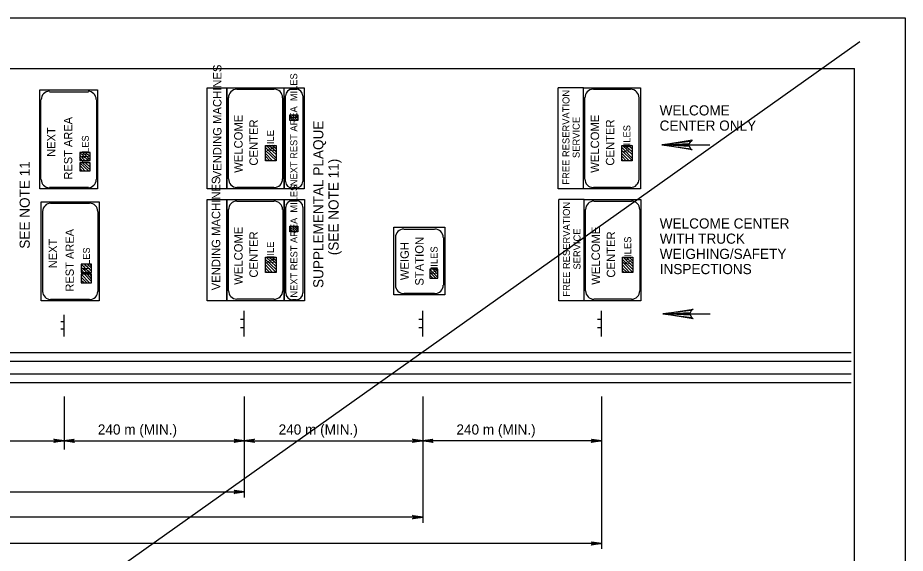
# Model space of a CAD drawing. Extents: x 2189973 to 2192941, y 2147557 to 2151454.
# Drawn here: x 2191872 to 2192732, y 2150935 to 2151454 of the extents above; entities that cross this region are included whole.
import ezdxf

# ---------------------------------------------------------------- set-up
doc = ezdxf.new("R2010")
doc.units = 0
for name, color, linetype in [('1', 7, 'Continuous'), ('Default', 7, 'Continuous'), ('PLT-BNDY', 7, 'Continuous')]:
    doc.layers.add(name, color=color, linetype=linetype)

# ---------------------------------------------------------------- blocks, each defined once
blk = doc.blocks.new('RARROW')
at = {"layer": 'Default'}
blk.add_lwpolyline([(-18.156, 2.28), (-17.479, 0.966), (0, 0), (-18.156, 2.28), (-19.086, 3.077), (0, 0), (-17.465, -0.864), (-18.103, -2.164), (0, 0), (-19.086, -3.033), (-18.103, -2.164)], dxfattribs=at)

msp = doc.modelspace()

# ---------------------------------------------------------------- linework, layer by layer
at = {"layer": '1'}
msp.add_line((2192688.33, 2151431.03), (2190039.06, 2149549.03), dxfattribs=at)
at = {"layer": 'Default'}
for p, q in [((2190104.48, 2151405.2), (2192683.21, 2151405.2)), ((2192683.21, 2149554.81), (2192683.21, 2151405.2)), ((2191893.03, 2151288.32), (2191893.03, 2151384.28)), ((2191893.03, 2151384.28), (2191949.21, 2151384.28)), ((2191902.46, 2151382.64), (2191940.19, 2151382.64)), ((2191949.21, 2151384.28), (2191949.21, 2151288.32)), ((2192074.62, 2151288.32), (2192074.62, 2151386.33)), ((2192074.62, 2151386.33), (2192129.98, 2151386.33)), ((2192084.05, 2151385.1), (2192120.14, 2151385.1)), ((2192138, 2151385.21), (2192141.59, 2151385.21)), ((2192395.73, 2151288.32), (2192395.73, 2151386.33)), ((2192420.34, 2151386.33), (2192395.73, 2151386.33)), ((2192420.34, 2151288.32), (2192420.34, 2151386.33)), ((2192420.34, 2151386.33), (2192475.7, 2151386.33)), ((2192430.18, 2151385.1), (2192465.86, 2151385.1)), ((2192475.7, 2151386.33), (2192475.7, 2151288.32)), ((2191894.26, 2151297.34), (2191894.26, 2151374.85)), ((2191947.98, 2151374.85), (2191947.98, 2151297.34)), ((2192076.26, 2151298.16), (2192076.26, 2151376.9)), ((2192128.59, 2151376.79), (2192128.59, 2151298.05)), ((2192129.98, 2151377.51), (2192129.98, 2151288.32)), ((2192131.4, 2151295.47), (2192131.4, 2151378.62)), ((2192148.18, 2151378.62), (2192148.18, 2151295.47)), ((2192421.57, 2151298.16), (2192421.57, 2151376.9)), ((2192474.06, 2151376.9), (2192474.06, 2151298.16)), ((2192140.89, 2151354.67), (2192135.57, 2151359.99)), ((2192138.73, 2151354.67), (2192135.57, 2151357.83)), ((2192136.57, 2151354.67), (2192135.57, 2151355.67)), ((2192143.06, 2151354.67), (2192137.48, 2151360.24)), ((2192143.31, 2151356.58), (2192139.64, 2151360.24)), ((2192143.31, 2151358.74), (2192141.81, 2151360.24)), ((2192496.21, 2151330.97), (2192542.96, 2151330.97)), ((2191949.21, 2151288.32), (2191893.03, 2151288.32)), ((2191940.19, 2151289.55), (2191902.46, 2151289.55)), ((2192129.98, 2151288.32), (2192074.62, 2151288.32)), ((2192120.14, 2151289.55), (2192084.05, 2151289.55)), ((2192141.65, 2151289.17), (2192138.06, 2151289.17)), ((2192420.34, 2151288.32), (2192395.73, 2151288.32)), ((2192475.7, 2151288.32), (2192420.34, 2151288.32)), ((2192465.86, 2151289.55), (2192430.18, 2151289.55)), ((2192055.35, 2151179.64), (2192055.35, 2151278.07)), ((2192055.35, 2151278.07), (2192074.62, 2151278.07)), ((2192074.62, 2151179.64), (2192074.62, 2151278.07)), ((2192074.62, 2151278.07), (2192129.98, 2151278.07)), ((2192074.62, 2151278.07), (2192074.62, 2151179.64)), ((2192129.98, 2151278.07), (2192129.98, 2151179.64)), ((2192129.98, 2151278.07), (2192129.98, 2151179.64)), ((2192138.16, 2151277.04), (2192141.75, 2151277.04)), ((2192396.55, 2151179.64), (2192396.55, 2151278.07)), ((2192421.16, 2151278.07), (2192396.55, 2151278.07)), ((2192421.16, 2151179.64), (2192421.16, 2151278.07)), ((2192421.16, 2151278.07), (2192476.11, 2151278.07)), ((2192476.11, 2151278.07), (2192476.11, 2151179.64)), ((2191894.54, 2151179.64), (2191894.54, 2151275.6)), ((2191894.54, 2151275.6), (2191950.72, 2151275.6)), ((2191903.56, 2151274.37), (2191941.29, 2151274.37)), ((2191950.72, 2151275.6), (2191950.72, 2151179.64)), ((2192084.05, 2151276.42), (2192120.14, 2151276.42)), ((2192131.57, 2151187.3), (2192131.57, 2151270.44)), ((2192148.35, 2151270.44), (2192148.35, 2151187.3)), ((2192430.59, 2151276.42), (2192467.09, 2151276.42)), ((2191896.18, 2151188.66), (2191896.18, 2151266.17)), ((2191949.49, 2151266.17), (2191949.49, 2151188.66)), ((2192076.26, 2151189.48), (2192076.26, 2151268.22)), ((2192128.75, 2151268.22), (2192128.75, 2151189.48)), ((2192422.39, 2151189.48), (2192422.39, 2151268.22)), ((2192474.88, 2151268.22), (2192474.88, 2151189.48)), ((2192141.06, 2151246.5), (2192135.73, 2151251.82)), ((2192143.22, 2151246.5), (2192137.65, 2151252.07)), ((2192143.47, 2151248.4), (2192139.81, 2151252.07)), ((2192143.47, 2151250.57), (2192141.97, 2151252.07)), ((2192138.89, 2151246.5), (2192135.73, 2151249.66)), ((2192136.73, 2151246.5), (2192135.73, 2151247.5)), ((2192236.61, 2151185.38), (2192236.61, 2151251)), ((2192236.61, 2151251), (2192285.82, 2151251)), ((2192246.45, 2151249.36), (2192275.98, 2151249.36)), ((2192285.82, 2151251), (2192285.82, 2151185.38)), ((2192238.25, 2151194.81), (2192238.25, 2151241.16)), ((2192284.59, 2151241.16), (2192284.59, 2151194.81)), ((2192285.82, 2151185.38), (2192236.61, 2151185.38)), ((2192275.98, 2151186.61), (2192246.45, 2151186.61)), ((2191950.72, 2151179.64), (2191894.54, 2151179.64)), ((2191941.29, 2151180.87), (2191903.56, 2151180.87)), ((2192074.62, 2151179.64), (2192055.35, 2151179.64)), ((2192129.98, 2151179.64), (2192074.62, 2151179.64)), ((2192120.14, 2151181.28), (2192084.05, 2151181.28)), ((2192141.75, 2151180.7), (2192138.16, 2151180.7)), ((2192421.16, 2151179.64), (2192396.55, 2151179.64)), ((2192476.11, 2151179.64), (2192421.16, 2151179.64)), ((2192467.09, 2151181.28), (2192430.59, 2151181.28)), ((2191916.68, 2151145.19), (2191916.68, 2151166.11)), ((2192091.43, 2151145.19), (2192091.43, 2151169.8)), ((2192264.5, 2151145.19), (2192264.5, 2151169.8)), ((2192437.97, 2151145.19), (2192437.97, 2151169.8)), ((2192497.22, 2151167.03), (2192543.15, 2151167.03)), ((2191916.68, 2151159.14), (2191913.4, 2151159.14)), ((2192091.43, 2151161.6), (2192087.74, 2151161.6)), ((2192264.5, 2151161.6), (2192260.81, 2151161.6)), ((2192437.97, 2151161.6), (2192433.87, 2151161.6)), ((2191916.68, 2151152.16), (2191913.4, 2151152.16)), ((2192091.43, 2151153.39), (2192087.74, 2151153.39)), ((2192264.5, 2151153.39), (2192260.81, 2151153.39)), ((2192437.97, 2151153.39), (2192433.87, 2151153.39)), ((2191186.33, 2151129.61), (2192679.93, 2151129.61)), ((2192509.33, 2151129.61), (2192509.33, 2151129.61)), ((2190114.32, 2151121), (2192679.93, 2151121)), ((2190114.32, 2151108.69), (2192679.93, 2151108.69)), ((2190114.32, 2151100.49), (2192679.93, 2151100.49)), ((2191916.68, 2151086.96), (2191916.68, 2151035.21)), ((2192091.43, 2151086.96), (2192091.43, 2150988.94)), ((2192264.5, 2151086.96), (2192264.5, 2150964.34)), ((2192437.97, 2151086.96), (2192437.97, 2150938.91)), ((2191714.55, 2151043.9), (2191916.68, 2151043.9)), ((2191916.68, 2151043.9), (2192091.43, 2151043.9)), ((2192091.43, 2151043.9), (2192264.5, 2151043.9)), ((2192437.97, 2151043.9), (2192264.5, 2151043.9)), ((2190939.04, 2150994.27), (2192091.43, 2150994.27)), ((2192264.5, 2150969.67), (2190939.04, 2150969.67)), ((2192437.97, 2150944.24), (2190939.04, 2150944.24))]:
    msp.add_line(p, q, dxfattribs=at)
for points in [[(2192074.62, 2151386.33), (2192074.62, 2151288.32), (2192055.35, 2151288.32), (2192055.35, 2151386.33)], [(2192129.98, 2151386.33), (2192149.53, 2151386.33), (2192149.53, 2151288.32), (2192129.98, 2151288.32)], [(2192143.31, 2151354.67), (2192135.57, 2151354.67), (2192135.57, 2151360.24), (2192143.31, 2151360.24)], [(2192122.19, 2151315.38), (2192111.94, 2151315.38), (2192111.94, 2151330.56), (2192122.19, 2151330.56)], [(2192467.5, 2151315.38), (2192457.66, 2151315.38), (2192457.66, 2151330.56), (2192467.5, 2151330.56)], [(2191941.83, 2151323.59), (2191931.99, 2151323.59), (2191931.99, 2151315.79), (2191941.83, 2151315.79)], [(2191941.83, 2151313.74), (2191931.99, 2151313.74), (2191931.99, 2151305.95), (2191941.83, 2151305.95)], [(2192129.98, 2151278.16), (2192149.7, 2151278.16), (2192149.7, 2151179.64), (2192129.98, 2151179.64)], [(2192143.47, 2151246.5), (2192135.73, 2151246.5), (2192135.73, 2151252.07), (2192143.47, 2151252.07)], [(2192122.19, 2151207.12), (2192111.94, 2151207.12), (2192111.94, 2151221.88), (2192122.19, 2151221.88)], [(2192468.32, 2151207.12), (2192458.07, 2151207.12), (2192458.07, 2151221.88), (2192468.32, 2151221.88)], [(2191943.34, 2151215.32), (2191933.09, 2151215.32), (2191933.09, 2151207.12), (2191943.34, 2151207.12)], [(2192279.26, 2151210.4), (2192271.47, 2151210.4), (2192271.47, 2151201.79), (2192279.26, 2151201.79)], [(2191943.34, 2151205.48), (2191933.09, 2151205.48), (2191933.09, 2151197.27), (2191943.34, 2151197.27)]]:
    msp.add_lwpolyline(points, close=True, dxfattribs=at)
for points in [[(2192122.19, 2151321.54), (2192112.76, 2151330.56)], [(2192122.19, 2151324.41), (2192115.22, 2151330.56)], [(2192122.19, 2151327.28), (2192118.09, 2151330.56)], [(2192122.19, 2151330.15), (2192120.96, 2151330.56)], [(2192467.5, 2151321.54), (2192458.07, 2151330.56)], [(2192467.5, 2151324.41), (2192460.94, 2151330.56)], [(2192467.5, 2151327.28), (2192463.81, 2151330.56)], [(2192467.5, 2151330.15), (2192467.09, 2151330.56)], [(2192524.5, 2151327.28), (2192523.27, 2151329.33), (2192496.21, 2151330.97), (2192524.5, 2151327.28), (2192525.73, 2151326.05), (2192496.21, 2151330.97), (2192523.27, 2151332.2), (2192524.5, 2151334.25), (2192496.21, 2151330.97), (2192525.73, 2151335.89), (2192524.5, 2151334.25)], [(2191940.19, 2151315.79), (2191931.99, 2151323.59)], [(2191936.91, 2151315.79), (2191931.99, 2151321.13)], [(2191941.83, 2151316.62), (2191934.86, 2151323.59)], [(2191941.83, 2151319.49), (2191937.32, 2151323.59)], [(2191941.83, 2151322.77), (2191940.6, 2151323.59)], [(2192122.19, 2151318.26), (2192111.94, 2151328.51)], [(2192122.19, 2151315.79), (2192111.94, 2151325.64)], [(2192118.91, 2151315.38), (2192111.94, 2151322.77)], [(2192467.5, 2151318.26), (2192457.66, 2151328.51)], [(2192467.5, 2151315.79), (2192457.66, 2151325.64)], [(2192464.63, 2151315.38), (2192457.66, 2151322.77)], [(2191934.04, 2151315.79), (2191931.99, 2151318.67)], [(2191940.19, 2151305.95), (2191931.99, 2151313.74)], [(2191941.83, 2151306.77), (2191934.45, 2151313.74)], [(2191941.83, 2151309.23), (2191937.32, 2151313.74)], [(2191941.83, 2151312.51), (2191940.6, 2151313.74)], [(2192116.04, 2151315.38), (2192111.94, 2151319.9)], [(2192113.17, 2151315.38), (2192111.94, 2151317.03)], [(2192461.76, 2151315.38), (2192457.66, 2151319.9)], [(2192458.89, 2151315.38), (2192457.66, 2151317.03)], [(2191936.91, 2151305.95), (2191931.99, 2151311.28)], [(2191934.04, 2151305.95), (2191931.99, 2151308)], [(2192122.19, 2151209.99), (2192111.94, 2151219.83)], [(2192122.19, 2151207.12), (2192111.94, 2151217.37)], [(2192122.19, 2151212.86), (2192112.76, 2151221.88)], [(2192122.19, 2151215.73), (2192115.22, 2151221.88)], [(2192122.19, 2151218.6), (2192118.09, 2151221.88)], [(2192122.19, 2151221.47), (2192120.96, 2151221.88)], [(2192468.32, 2151209.99), (2192458.07, 2151219.83)], [(2192468.32, 2151207.12), (2192458.07, 2151217.37)], [(2192468.32, 2151212.86), (2192458.89, 2151221.88)], [(2192468.32, 2151215.73), (2192461.76, 2151221.88)], [(2192468.32, 2151218.6), (2192464.63, 2151221.88)], [(2192468.32, 2151221.47), (2192467.5, 2151221.88)], [(2191941.29, 2151207.12), (2191933.09, 2151215.32)], [(2191938.83, 2151207.12), (2191933.09, 2151212.45)], [(2191935.96, 2151207.12), (2191933.09, 2151209.99)], [(2191943.34, 2151208.35), (2191936.37, 2151215.32)], [(2191943.34, 2151211.22), (2191939.24, 2151215.32)], [(2191943.34, 2151213.68), (2191942.11, 2151215.32)], [(2192118.91, 2151207.12), (2192111.94, 2151214.5)], [(2192116.04, 2151207.12), (2192111.94, 2151211.22)], [(2192113.17, 2151207.12), (2192111.94, 2151208.35)], [(2192279.26, 2151202.2), (2192271.47, 2151209.99)], [(2192279.26, 2151205.07), (2192274.34, 2151210.4)], [(2192279.26, 2151207.94), (2192277.21, 2151210.4)], [(2192465.04, 2151207.12), (2192458.07, 2151214.5)], [(2192462.58, 2151207.12), (2192458.07, 2151211.22)], [(2192459.71, 2151207.12), (2192458.07, 2151208.35)], [(2191941.29, 2151197.27), (2191933.09, 2151205.48)], [(2191938.83, 2151197.27), (2191933.09, 2151202.61)], [(2191943.34, 2151198.51), (2191936.37, 2151205.48)], [(2191943.34, 2151200.97), (2191939.24, 2151205.48)], [(2191943.34, 2151203.84), (2191942.11, 2151205.48)], [(2192277.21, 2151201.79), (2192271.47, 2151207.53)], [(2192274.34, 2151201.79), (2192271.47, 2151204.66)], [(2191935.96, 2151197.27), (2191933.09, 2151199.33)], [(2192525.52, 2151163.34), (2192524.29, 2151165.8), (2192497.22, 2151167.03), (2192525.52, 2151163.34), (2192526.75, 2151162.11), (2192497.22, 2151167.03), (2192524.29, 2151168.26), (2192525.11, 2151170.31), (2192497.22, 2151167.03), (2192526.75, 2151171.54), (2192525.11, 2151170.31)]]:
    msp.add_lwpolyline(points, dxfattribs=at)
for centre, radius, start, end in [((2191902.46, 2151374.97), 8.02, 90, 180), ((2191939.88, 2151374.97), 8.02, 0, 90), ((2192084.18, 2151376.79), 8.16, 90, 180), ((2192120.21, 2151376.72), 8.38, 0.4758, 90.4758), ((2192138, 2151378.62), 6.59, 90, 180), ((2192141.59, 2151378.62), 6.59, 0, 90), ((2192429.86, 2151376.79), 8.16, 90, 180), ((2192466.1, 2151376.79), 8.16, 0, 90), ((2191902.46, 2151297.46), 8.02, 180, 270), ((2191939.88, 2151297.46), 8.02, 270, 0), ((2192084.45, 2151297.89), 8.19, 178.09918, 268.09918), ((2192120.11, 2151298.02), 8.48, 270.18711, 0.18711), ((2192137.88, 2151295.65), 6.48, 181.57387, 271.57387), ((2192141.77, 2151295.59), 6.42, 268.939, 358.939), ((2192429.86, 2151297.86), 8.16, 180, 270), ((2192466.1, 2151297.86), 8.16, 270, 0), ((2192138.16, 2151270.44), 6.59, 90, 180), ((2192141.75, 2151270.44), 6.59, 0, 90), ((2191903.89, 2151266.34), 8.02, 90, 180), ((2191941.31, 2151266.34), 8.02, 0, 90), ((2192084.26, 2151268.43), 8, 91.4688, 181.4688), ((2192120.29, 2151268.12), 8.3, 1.02511, 91.02511), ((2192430.57, 2151268.27), 8.16, 90, 180), ((2192466.82, 2151268.27), 8.16, 0, 90), ((2192246.22, 2151241.12), 8.16, 90, 180), ((2192276.16, 2151241.12), 8.16, 0, 90), ((2192246.22, 2151194.85), 8.16, 180, 270), ((2192276.16, 2151194.85), 8.16, 270, 0), ((2191903.89, 2151188.83), 8.02, 180, 270), ((2191941.31, 2151188.83), 8.02, 270, 0), ((2192084.26, 2151189.28), 8, 178.5312, 268.5312), ((2192120.35, 2151189.69), 8.41, 268.60282, 358.60282), ((2192138.16, 2151187.3), 6.59, 180, 270), ((2192141.75, 2151187.3), 6.59, 270, 0), ((2192430.57, 2151189.34), 8.16, 180, 270), ((2192466.82, 2151189.34), 8.16, 270, 0)]:
    msp.add_arc(centre, radius, start, end, dxfattribs=at)
at = {"layer": 'PLT-BNDY'}
msp.add_lwpolyline([(2189973.25, 2151454.41), (2192732.43, 2151454.41), (2192732.43, 2149505.6), (2189973.25, 2149505.6)], close=True, dxfattribs=at)

# ---------------------------------------------------------------- block references
at = {"layer": 'Default', "xscale": 0.515679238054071, "yscale": 0.5369477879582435}
for p in [(2191916.68, 2151043.9), (2192091.43, 2151043.9), (2192264.5, 2151043.9), (2192437.97, 2151043.9), (2192091.43, 2150994.27), (2192264.5, 2150969.67), (2192437.97, 2150944.24)]:
    msp.add_blockref('RARROW', p, dxfattribs=at)
at = {"layer": 'Default', "xscale": 0.515679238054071, "yscale": 0.5369477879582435, "rotation": 180}
for p in [(2191916.68, 2151043.9), (2192091.43, 2151043.9), (2192264.5, 2151043.9)]:
    msp.add_blockref('RARROW', p, dxfattribs=at)

# ---------------------------------------------------------------- texts
at = {"layer": 'Default'}
for s, height, p in [('VENDING MACHINES', 8.1619, (2192069.29, 2151298.57)), ('NEXT REST AREA  MILES', 6.729, (2192142.77, 2151290.95)), ('FREE RESERVATION', 6.7987, (2192406.8, 2151292.42)), ('REST AREA', 8.014, (2191924.61, 2151297.34)), ('WELCOME', 8.162, (2192089.79, 2151303.9)), ('CENTER', 8.162, (2192104.56, 2151310.87)), ('SERVICE', 6.799, (2192416.65, 2151318.26)), ('WELCOME', 8.162, (2192435.51, 2151303.9)), ('CENTER', 8.162, (2192450.28, 2151310.87)), ('NEXT', 8.014, (2191908.2, 2151319.49)), ('SUPPLEMENTAL PLAQUE', 9.8425, (2192168.14, 2151192.16)), ('   MILES', 6.801, (2192465.86, 2151315.38)), ('   MILES', 6.678, (2191940.6, 2151305.95)), ('   MILE', 6.801, (2192120.14, 2151316.61)), ('SEE NOTE 11', 9.8425, (2191883.38, 2151230.27)), ('(SEE NOTE 11)', 9.8425, (2192182.91, 2151223.93)), ('VENDING MACHINES', 8.1619, (2192068.06, 2151189.89)), ('NEXT REST AREA  MILES', 6.729, (2192142.93, 2151182.78)), ('FREE RESERVATION', 6.7987, (2192407.21, 2151183.74)), ('WELCOME', 8.162, (2192089.79, 2151195.22)), ('WELCOME', 8.162, (2192436.33, 2151195.22)), ('REST AREA', 8.014, (2191926.11, 2151188.66)), ('CENTER', 8.162, (2192104.56, 2151202.2)), ('SERVICE', 6.799, (2192417.47, 2151209.99)), ('CENTER', 8.162, (2192451.1, 2151202.2)), ('NEXT', 8.014, (2191909.71, 2151211.22)), ('   MILE', 6.801, (2192120.14, 2151208.35)), ('WEIGH', 8.162, (2192250.96, 2151199.73)), ('STATION', 8.162, (2192265.32, 2151194.4)), ('   MILES', 6.801, (2192466.68, 2151207.12)), ('   MILES', 6.678, (2191941.7, 2151197.27)), ('  MILES', 6.801, (2192278.85, 2151200.15))]:
    msp.add_text(s, height=height, rotation=90, dxfattribs=at).set_placement(p)
for s, height, p in [('WELCOME', 9.842, (2192494.22, 2151359.58)), ('CENTER ONLY', 9.8425, (2192494.22, 2151344.81)), ('WELCOME CENTER', 9.8425, (2192494.33, 2151249.84)), ('WITH TRUCK', 9.842, (2192494.33, 2151235.08)), ('WEIGHING/SAFETY', 9.8425, (2192494.33, 2151220.31)), ('INSPECTIONS', 9.8425, (2192494.33, 2151205.55)), ('240 m (MIN.)', 9.8425, (2191949.41, 2151049.88)), ('240 m (MIN.)', 9.8425, (2192124.74, 2151049.88)), ('240 m (MIN.)', 9.8425, (2192297.17, 2151049.88))]:
    msp.add_text(s, height=height, dxfattribs=at).set_placement(p)

doc.saveas('drawing.dxf')
